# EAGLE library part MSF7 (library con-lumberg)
MSF CONNECTOR
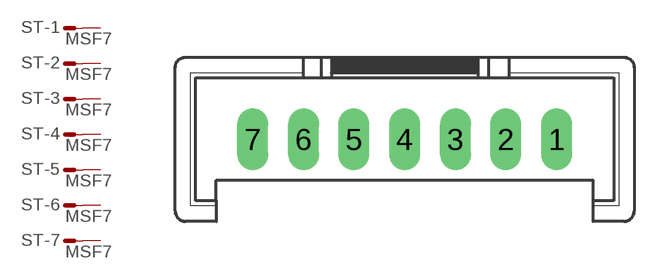
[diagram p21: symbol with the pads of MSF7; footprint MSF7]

Designator prefix ST; gates -1=M -2=M -3=M -4=M -5=M -6=M -7=M

## MSF7 (OC_FARNELL: unknown; OC_NEWARK: unknown)  [MSF7]
1  -1:S  pas
2  -2:S  pas
3  -3:S  pas
4  -4:S  pas
5  -5:S  pas
6  -6:S  pas
7  -7:S  pas

## Footprint MSF7 (pad centres in mm)
MSF CONNECTOR
drill 1.016 long: 1 7.518,-2.54; 2 5.004,-2.54; 3 2.515,-2.54; 4 0,-2.54; 5 -2.515,-2.54; 6 -5.004,-2.54; 7 -7.518,-2.54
